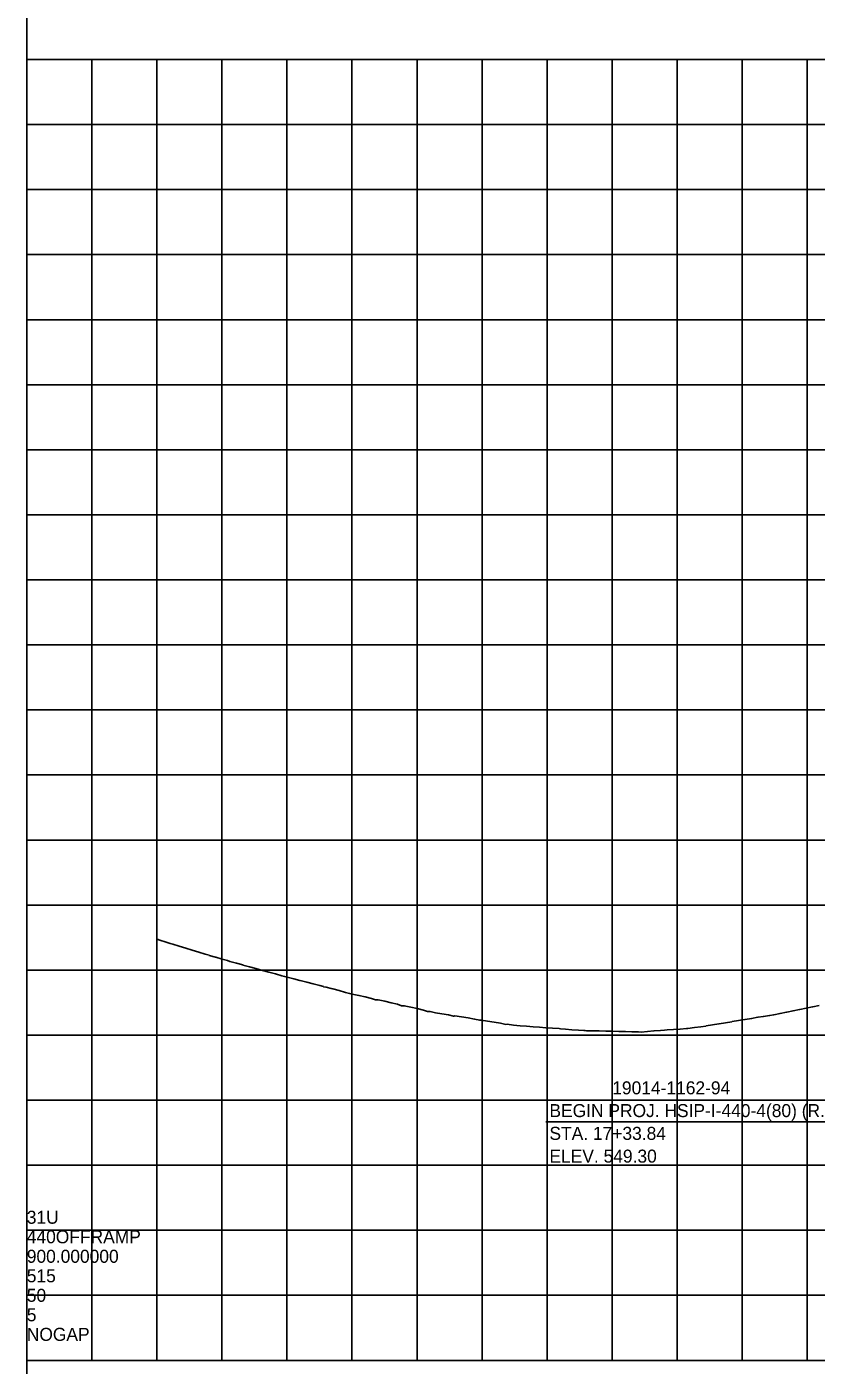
# Model space of a CAD drawing. Extents: x 1724534 to 1727318, y 654728 to 660023.
# Drawn here: x 1725889 to 1726496, y 657224 to 658253 of the extents above; entities that cross this region are included whole.
import ezdxf

# ---------------------------------------------------------------- set-up
doc = ezdxf.new("R2010")
doc.units = 0
for name, color, linetype in [('DESIGN - CENTERLINE - Proposed Text', 7, 'Continuous'), ('DESIGN - SHEET - Light Grid', 7, 'Continuous'), ('SURVEY - PROFILE - Ground Line with Text', 7, 'Continuous')]:
    doc.layers.add(name, color=color, linetype=linetype)

msp = doc.modelspace()

# ---------------------------------------------------------------- linework, layer by layer
at = {"layer": 'DESIGN - CENTERLINE - Proposed Text'}
msp.add_line((1726651.9, 657411), (1726287.7, 657411), dxfattribs=at)
at = {"layer": 'DESIGN - SHEET - Light Grid'}
for p, q in [((1725888.6, 657227.6), (1725888.6, 659727.6)), ((1727288.6, 658227.6), (1725888.6, 658227.6)), ((1725888.6, 658227.6), (1725888.6, 657227.6)), ((1725938.6, 657227.6), (1725938.6, 658227.6)), ((1725988.6, 657227.6), (1725988.6, 658227.6)), ((1726038.6, 657227.6), (1726038.6, 658227.6)), ((1726088.6, 657227.6), (1726088.6, 658227.6)), ((1726138.6, 657227.6), (1726138.6, 658227.6)), ((1726188.6, 657227.6), (1726188.6, 658227.6)), ((1726238.6, 657227.6), (1726238.6, 658227.6)), ((1726288.6, 657227.6), (1726288.6, 658227.6)), ((1726338.6, 657227.6), (1726338.6, 658227.6)), ((1726388.6, 657227.6), (1726388.6, 658227.6)), ((1726438.6, 657227.6), (1726438.6, 658227.6)), ((1726488.6, 657227.6), (1726488.6, 658227.6)), ((1725888.6, 658177.6), (1727288.6, 658177.6)), ((1725888.6, 658127.6), (1727288.6, 658127.6)), ((1725888.6, 658077.6), (1727288.6, 658077.6)), ((1725888.6, 658027.6), (1727288.6, 658027.6)), ((1725888.6, 657977.6), (1727288.6, 657977.6)), ((1725888.6, 657927.6), (1727288.6, 657927.6)), ((1725888.6, 657877.6), (1727288.6, 657877.6)), ((1725888.6, 657827.6), (1727288.6, 657827.6)), ((1725888.6, 657777.6), (1727288.6, 657777.6)), ((1725888.6, 657727.6), (1727288.6, 657727.6)), ((1725888.6, 657677.6), (1727288.6, 657677.6)), ((1725888.6, 657627.6), (1727288.6, 657627.6)), ((1725888.6, 657577.6), (1727288.6, 657577.6)), ((1725888.6, 657527.6), (1727288.6, 657527.6)), ((1725888.6, 657477.6), (1727288.6, 657477.6)), ((1725888.6, 657427.6), (1727288.6, 657427.6)), ((1725888.6, 657377.6), (1727288.6, 657377.6)), ((1725888.6, 657327.6), (1727288.6, 657327.6)), ((1725888.6, 657277.6), (1727288.6, 657277.6)), ((1725888.6, 657227.6), (1727088.6, 657227.6)), ((1725888.6, 657227.6), (1725888.6, 654727.6)), ((1725888.6, 657227.6), (1727288.6, 657227.6))]:
    msp.add_line(p, q, dxfattribs=at)
at = {"layer": 'SURVEY - PROFILE - Ground Line with Text'}
for points in [[(1725988.6, 657551.3), (1725988.8, 657551.3), (1725990.8, 657550.7), (1725990.8, 657550.7), (1725995.8, 657549.1), (1725995.8, 657549.1), (1725998.8, 657548.1), (1726000.8, 657547.5), (1726000.8, 657547.5), (1726005.8, 657546), (1726005.8, 657546), (1726010.8, 657544.5), (1726010.8, 657544.5), (1726015.8, 657543), (1726015.8, 657542.9), (1726020.8, 657541.4), (1726020.8, 657541.4), (1726020.8, 657541.4), (1726025.7, 657539.9), (1726025.8, 657539.9), (1726026.8, 657539.6), (1726028.8, 657539), (1726028.9, 657538.9), (1726033.8, 657537.5), (1726033.9, 657537.5), (1726038.8, 657536.1), (1726038.9, 657536.1), (1726042.8, 657534.9), (1726044.8, 657534.3), (1726044.8, 657534.3), (1726049.8, 657532.9), (1726049.8, 657532.9), (1726049.8, 657532.9), (1726054.8, 657531.6), (1726054.8, 657531.5), (1726059.8, 657530.2), (1726059.8, 657530.2), (1726064.8, 657528.8), (1726064.8, 657528.8), (1726069.8, 657527.4), (1726069.8, 657527.4), (1726074.8, 657526), (1726074.8, 657526), (1726079.8, 657524.7), (1726079.8, 657524.7), (1726084.8, 657523.3), (1726084.8, 657523.3), (1726086.8, 657522.7), (1726086.8, 657522.7), (1726088.8, 657522.2), (1726088.8, 657522.2), (1726093.8, 657520.9), (1726093.8, 657520.9), (1726098.4, 657519.7), (1726098.4, 657519.7), (1726098.8, 657519.6), (1726103.8, 657518.3), (1726103.8, 657518.3), (1726108.8, 657517), (1726108.8, 657517), (1726113.8, 657515.7), (1726116.7, 657514.9), (1726116.8, 657514.8), (1726118.8, 657514.4), (1726118.8, 657514.4), (1726122.5, 657513.5), (1726123.8, 657513.1), (1726123.8, 657513.1), (1726123.9, 657513.1), (1726128.8, 657511.8), (1726133.7, 657510.5), (1726136.7, 657509.7), (1726136.8, 657509.7), (1726138.8, 657509.2), (1726138.8, 657509.2), (1726143.8, 657508.1), (1726143.9, 657508.1), (1726148.8, 657507), (1726153.7, 657505.8), (1726156.7, 657504.7), (1726156.8, 657504.7), (1726158.8, 657504.7), (1726158.8, 657504.7), (1726163.8, 657503.6), (1726163.8, 657503.6), (1726168.8, 657502.5), (1726173.7, 657501.3), (1726176.7, 657500.1), (1726176.8, 657500.1), (1726178.8, 657500.2), (1726178.8, 657500.2), (1726183.8, 657499.1), (1726188.8, 657498), (1726193.7, 657496.8), (1726196.7, 657495.9), (1726196.8, 657495.9), (1726198.8, 657495.7), (1726198.8, 657495.7), (1726202.8, 657494.8), (1726207.8, 657494), (1726212.8, 657493.2)], [(1726212.8, 657493.2), (1726216.7, 657492.2), (1726216.8, 657492.2), (1726216.8, 657492.2), (1726217.8, 657492.4), (1726222.8, 657491.6), (1726227.8, 657490.8), (1726232.8, 657490), (1726236.8, 657489), (1726236.8, 657489), (1726237.8, 657489.2), (1726242.8, 657488.4), (1726247.8, 657487.6), (1726252.8, 657486.8), (1726256.8, 657485.9), (1726257.8, 657486), (1726262.8, 657485.2), (1726267.8, 657484.8), (1726272.8, 657484.4), (1726272.8, 657484.4), (1726277.8, 657484.1), (1726282.8, 657483.7), (1726287.7, 657483.3), (1726292.7, 657483), (1726292.8, 657483), (1726297.8, 657482.6), (1726298.8, 657482.5), (1726302.8, 657482.2), (1726307.7, 657481.8), (1726312.7, 657481.5), (1726312.8, 657481.5), (1726316.8, 657481.1), (1726317.8, 657481.1), (1726318.8, 657481), (1726323.8, 657480.9), (1726328.7, 657480.8), (1726333.7, 657480.7), (1726333.8, 657480.7), (1726338.8, 657480.6), (1726343.7, 657480.4), (1726348.7, 657480.3), (1726348.8, 657480.3), (1726353.8, 657480.2), (1726358.8, 657480.1), (1726360.8, 657480), (1726365.7, 657480.4), (1726370.7, 657480.8), (1726370.8, 657480.8), (1726375.8, 657481.2), (1726378.8, 657481.4), (1726380.8, 657481.6), (1726385.7, 657482), (1726390.7, 657482.3), (1726390.9, 657482.3), (1726395.8, 657482.7), (1726396.8, 657482.8), (1726396.9, 657482.8), (1726396.9, 657482.8), (1726401.8, 657483.5), (1726401.9, 657483.5), (1726406.8, 657484.1), (1726410.7, 657484.6), (1726410.8, 657484.7), (1726415.7, 657485.5), (1726415.8, 657485.5), (1726420.7, 657486.3), (1726420.8, 657486.3), (1726425.7, 657487.1), (1726425.8, 657487.1), (1726430.7, 657487.9), (1726430.8, 657488), (1726430.8, 657488), (1726435.7, 657488.8), (1726435.8, 657488.8), (1726440.7, 657489.6), (1726440.8, 657489.6), (1726445.7, 657490.4), (1726445.8, 657490.4), (1726450.7, 657491.3), (1726450.8, 657491.3), (1726454.8, 657491.9), (1726454.8, 657491.9), (1726459.8, 657492.8), (1726462.7, 657493.3), (1726462.8, 657493.3), (1726467.7, 657494.3), (1726467.8, 657494.3), (1726472.7, 657495.3), (1726472.8, 657495.3), (1726477.7, 657496.3), (1726477.8, 657496.3), (1726482.7, 657497.3), (1726482.8, 657497.3), (1726487.7, 657498.3), (1726487.8, 657498.3), (1726492.7, 657499.3), (1726492.8, 657499.3), (1726497.7, 657500.3)]]:
    msp.add_lwpolyline(points, dxfattribs=at)

# ---------------------------------------------------------------- texts
at = {"layer": 'DESIGN - CENTERLINE - Proposed Text'}
for s, p in [('             19014-1162-94', (1726290.4, 657432.1)), ('BEGIN PROJ. HSIP-I-440-4(80) (R.O.W.)', (1726290.4, 657414.6)), ('STA. 17+33.84', (1726290.4, 657397.1)), ('ELEV. 549.30', (1726290.4, 657379.6))]:
    msp.add_text(s, height=10, rotation=360, dxfattribs=at).set_placement(p)
at = {"layer": 'DESIGN - SHEET - Light Grid'}
for s, p in [('31U', (1725888.6, 657332.6)), ('440OFFRAMP', (1725888.6, 657317.6)), ('900.000000', (1725888.6, 657302.6)), ('515', (1725888.6, 657287.6)), ('50', (1725888.6, 657272.6)), ('5', (1725888.6, 657257.6)), ('NOGAP', (1725888.6, 657242.6))]:
    msp.add_text(s, height=10, dxfattribs=at).set_placement(p)

doc.saveas('drawing.dxf')
